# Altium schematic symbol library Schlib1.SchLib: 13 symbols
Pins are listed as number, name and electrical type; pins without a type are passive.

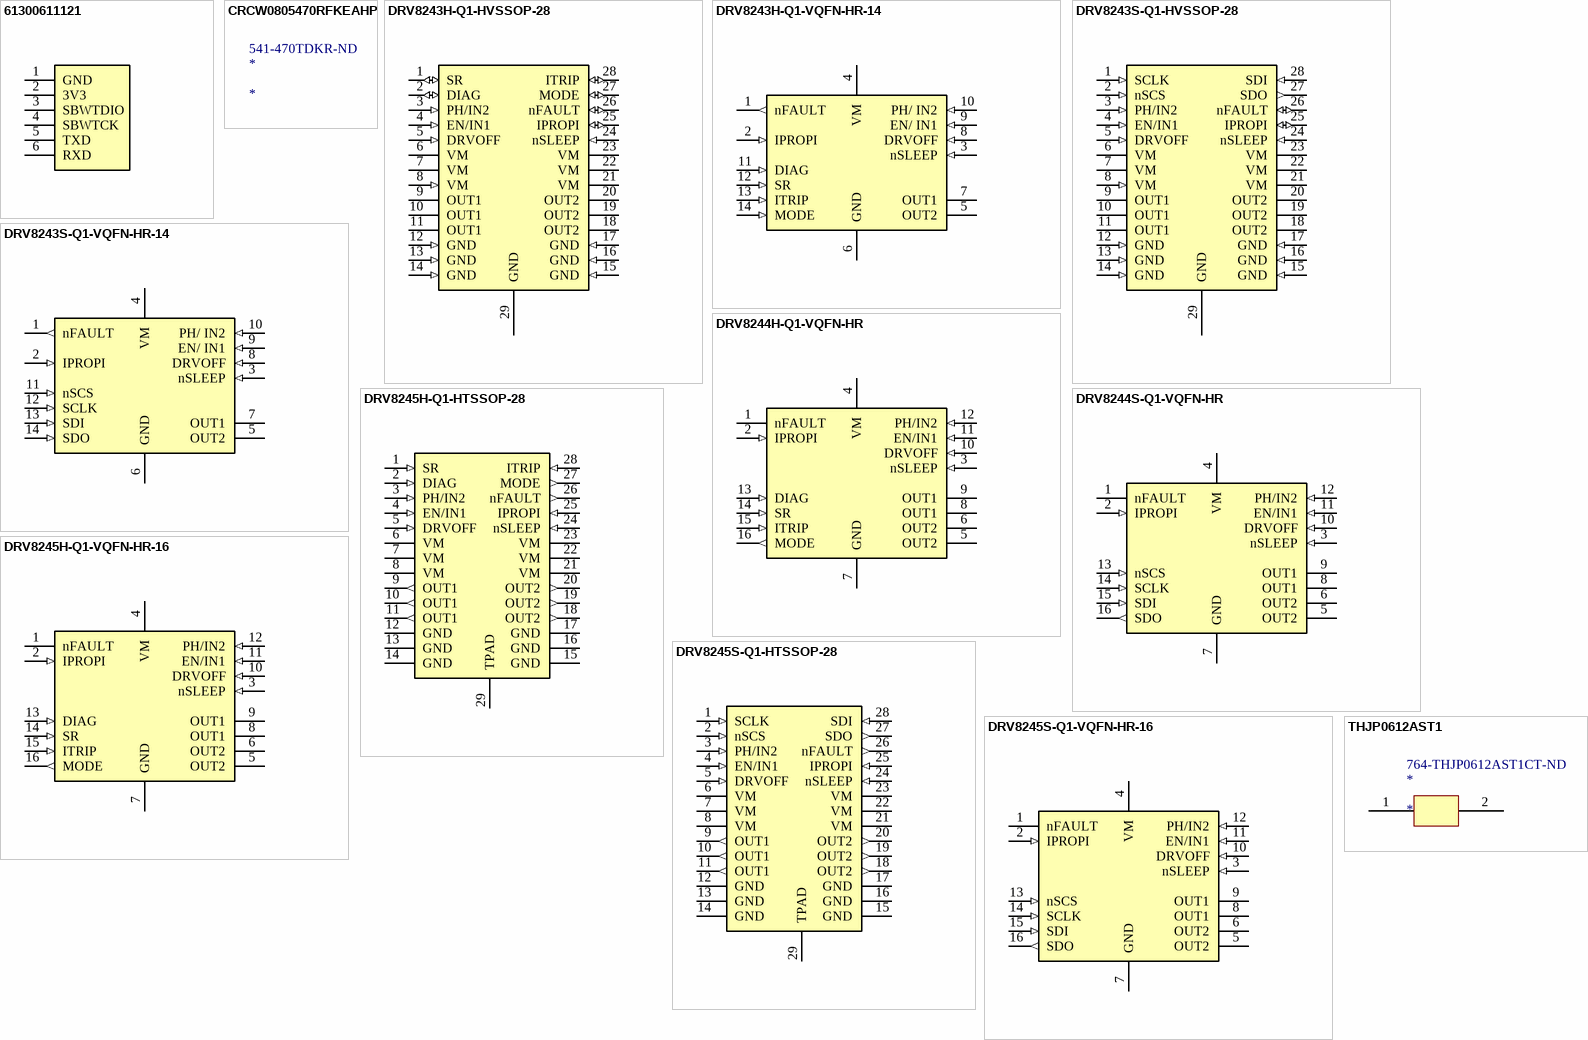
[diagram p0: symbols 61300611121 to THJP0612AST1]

## 61300611121
designator U?, comment Used in BOM report
WURTH ELEKTRONIK - 61300611121 - Pin Header, Board-to-Board, 2.54 mm, 1 Rows, 6 Contacts, Through Hole, WR-PHD Series; CompType: Used in some BOM reports.  Useful for finding later.; Current Rating: 3A; Voltage Rating: 250V; Number of Positions: 6; Gender: Male; Connector Type: Male Pin; Pitch: 0.1inch
pins: 1 GND (power) "3V3", 2 3V3, 3 SBWTDIO, 4 SBWTCK, 5 TXD, 6 RXD

## CRCW0805470RFKEAHP
designator *  Supplier Part Number 1: 541-470TDKR-ND
Surface Mount Chip Resistor, Thick Film, AEC-Q200 CRCW Series, 470 ohm, 330 mW, 1%, 150 V ;RoHS Compliant: Yes; Manufacturer: Vishay; Manufacturer Part Number: CRCW0805470RFKEAHP; Resistance: 470R; Power Rating: 330mW; Voltage Rating: 150V; Max Power Dissipation: 333mW; Temperature Coefficient: 100ppm/°C
footprint 0805

## DRV8243H-Q1-HVSSOP-28
designator U?, comment DRV8243H-Q1
Manufacturer: Texas Instruments; CompType: Used in some BOM reports.  Useful for finding later.
footprint HVSSOP-28
pins: 1 SR (io), 2 DIAG (io), 3 PH/IN2 (in), 4 EN/IN1 (in), 5 DRVOFF (in), 6 VM (power), 7 VM (power), 8 VM (in), 9 OUT1 (power), 10 OUT1 (power), 11 OUT1 (power), 12 GND (in), 13 GND (in), 14 GND (in), 15 GND (in), 16 GND (in), 17 GND (in), 18 OUT2 (power), 19 OUT2 (power), 20 OUT2 (power), 21 VM (power), 22 VM (power), 23 VM (power), 24 nSLEEP (in), 25 IPROPI (io), 26 nFAULT (io), 27 MODE (io), 28 ITRIP (io), 29 GND (power) "Thermal Pad"

## DRV8243H-Q1-VQFN-HR-14
designator U?, comment DRV8243H-Q1
Manufacturer: Texas Instruments; CompType: Used in some BOM reports.  Useful for finding later.
footprint VQFN-HR (14)
pins: 1 nFAULT (out), 2 IPROPI (in), 3 nSLEEP (in), 4 VM (power), 5 OUT2 (power), 6 GND (power), 7 OUT1 (power), 8 DRVOFF (in), 9 EN/ IN1 (in), 10 PH/ IN2 (in), 11 DIAG (in), 12 SR (in), 13 ITRIP (in), 14 MODE (in)

## DRV8243S-Q1-HVSSOP-28
designator U?, comment Used in BOM report
DRV8243S-Q1 HVSSOP-28; CompType: Used in some BOM reports.  Useful for finding later.
footprint HTSSOP28
footprint HVSSOP-28
pins: 1 SCLK (in), 2 nSCS (in), 3 PH/IN2 (in), 4 EN/IN1 (in), 5 DRVOFF (in), 6 VM (power), 7 VM (power), 8 VM (in), 9 OUT1 (power), 10 OUT1 (power), 11 OUT1 (power), 12 GND (in), 13 GND (in), 14 GND (in), 15 GND (in), 16 GND (in), 17 GND (in), 18 OUT2 (power), 19 OUT2 (power), 20 OUT2 (power), 21 VM (power), 22 VM (power), 23 VM (power), 24 nSLEEP (in), 25 IPROPI (io), 26 nFAULT (io), 27 SDO (out), 28 SDI (in), 29 GND (power) "thermal-pad"

## DRV8243S-Q1-VQFN-HR-14
designator U?, comment DRV8243S-Q1
Manufacturer: Texas Instruments; CompType: Used in some BOM reports.  Useful for finding later.
footprint VQFN-HR (14)
pins: 1 nFAULT (out), 2 IPROPI (in), 3 nSLEEP (in), 4 VM (power), 5 OUT2 (power), 6 GND (power), 7 OUT1 (power), 8 DRVOFF (in), 9 EN/ IN1 (in), 10 PH/ IN2 (in), 11 nSCS (in), 12 SCLK (in), 13 SDI (in), 14 SDO (in)

## DRV8244H-Q1-VQFN-HR
designator U?, comment DRV8244H-Q1
Manufacturer: Texas Instruments; CompType: Used in some BOM reports.  Useful for finding later.
footprint VQFN-HR (DRV8x44)
pins: 1 nFAULT (oc), 2 IPROPI (in), 3 nSLEEP (in), 4 VM (power), 5 OUT2 (power), 6 OUT2 (power), 7 GND (power), 8 OUT1 (power), 9 OUT1 (power), 10 DRVOFF (in), 11 EN/IN1 (in), 12 PH/IN2 (in), 13 DIAG (in), 14 SR (in), 15 ITRIP (in), 16 MODE (out)

## DRV8244S-Q1-VQFN-HR
designator U?, comment DRV8244S-Q1
Manufacturer: Texas Instruments; CompType: Used in some BOM reports.  Useful for finding later.
footprint VQFN-HR (DRV8x44)
pins: 1 nFAULT (oc), 2 IPROPI (in), 3 nSLEEP (in), 4 VM (power), 5 OUT2 (power), 6 OUT2 (power), 7 GND (power), 8 OUT1 (power), 9 OUT1 (power), 10 DRVOFF (in), 11 EN/IN1 (in), 12 PH/IN2 (in), 13 nSCS (in), 14 SCLK (in), 15 SDI (in), 16 SDO (out)

## DRV8245H-Q1-HTSSOP-28
designator U?, comment DRV8245SH-Q1
DRV8245H-Q1 HTSSOP 28-pin leaded package; Manufacturer: Used in BOM report; CompType: Used in some BOM reports.  Useful for finding later.
footprint HTSSOP-28-epod
pins: 1 SR (in), 2 DIAG (in), 3 PH/IN2 (in), 4 EN/IN1 (in), 5 DRVOFF (in), 6 VM (power), 7 VM (power), 8 VM (power), 9 OUT1 (out), 10 OUT1 (out), 11 OUT1 (out), 12 GND, 13 GND, 14 GND, 15 GND, 16 GND, 17 GND, 18 OUT2 (out), 19 OUT2 (out), 20 OUT2 (out), 21 VM (power), 22 VM (power), 23 VM (power), 24 nSLEEP (in), 25 IPROPI (in), 26 nFAULT (out), 27 MODE (out), 28 ITRIP (in), 29 TPAD

## DRV8245H-Q1-VQFN-HR-16
designator U?, comment DRV8245H-Q1
Manufacturer: Texas Instruments; CompType: Used in some BOM reports.  Useful for finding later.
footprint VQFN-HR (16)
pins: 1 nFAULT (oc), 2 IPROPI (in), 3 nSLEEP (in), 4 VM (power), 5 OUT2 (power), 6 OUT2 (power), 7 GND (power), 8 OUT1 (power), 9 OUT1 (power), 10 DRVOFF (in), 11 EN/IN1 (in), 12 PH/IN2 (in), 13 DIAG (in), 14 SR (in), 15 ITRIP (in), 16 MODE (out)

## DRV8245S-Q1-HTSSOP-28
designator U?, comment DRV8245SH-Q1
DRV8245S-Q1 HTSSOP 28-pin leaded package; Manufacturer: Used in BOM report; CompType: Used in some BOM reports.  Useful for finding later.
footprint HTSSOP-28-epod
pins: 1 SCLK (in), 2 nSCS    (in), 3 PH/IN2 (in), 4 EN/IN1 (in), 5 DRVOFF (in), 6 VM (power), 7 VM (power), 8 VM (power), 9 OUT1 (out), 10 OUT1 (out), 11 OUT1 (out), 12 GND, 13 GND, 14 GND, 15 GND, 16 GND, 17 GND, 18 OUT2 (out), 19 OUT2 (out), 20 OUT2 (out), 21 VM (power), 22 VM (power), 23 VM (power), 24 nSLEEP (in), 25 IPROPI (in), 26 nFAULT (out), 27 SDO (out), 28 SDI (in), 29 TPAD

## DRV8245S-Q1-VQFN-HR-16
designator U?, comment DRV8245S-Q1
Manufacturer: Texas Instruments; CompType: Used in some BOM reports.  Useful for finding later.
footprint VQFN-HR (16)
pins: 1 nFAULT (oc), 2 IPROPI (in), 3 nSLEEP (in), 4 VM (power), 5 OUT2 (power), 6 OUT2 (power), 7 GND (power), 8 OUT1 (power), 9 OUT1 (power), 10 DRVOFF (in), 11 EN/IN1 (in), 12 PH/IN2 (in), 13 nSCS (in), 14 SCLK (in), 15 SDI (in), 16 SDO (out)

## THJP0612AST1
designator *  Supplier Part Number 1: 764-THJP0612AST1CT-ND
Thermal Jumper; Manufacturer: Vishay; Manufacturer Part Number: THJP0612AST1
footprint 0612
pins: 1, 2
